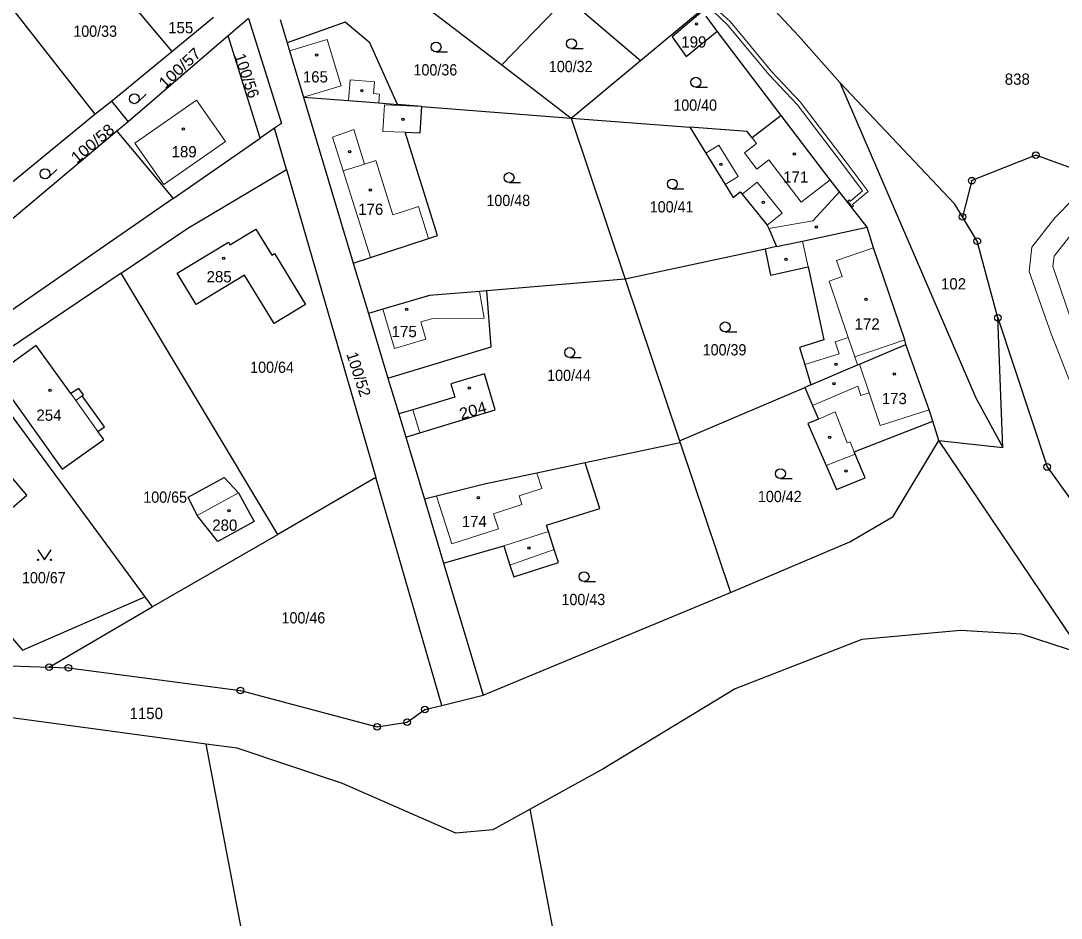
# Model space of a CAD drawing. Extents: x -758887 to -754328, y -1031688 to -1029144.
# Drawn here: x -756179.9 to -756022.6, y -1030649.6 to -1030514 of the extents above; entities that cross this region are included whole.
import ezdxf
from ezdxf.enums import TextEntityAlignment as Align

# ---------------------------------------------------------------- set-up
doc = ezdxf.new("R2010")
doc.units = 0
doc.header["$LTSCALE"] = 0.68
for name, color, linetype, lineweight in [('1', 7, 'Continuous', 25), ('13', 7, 'Continuous', 13), ('3', 7, 'Continuous', 25), ('4', 7, 'Continuous', 13), ('5', 7, 'Continuous', 25), ('8', 7, 'Continuous', 25)]:
    doc.layers.add(name, color=color, linetype=linetype, lineweight=lineweight)
doc.layers.add('2', color=7, linetype='Continuous')

msp = doc.modelspace()

# ---------------------------------------------------------------- linework, layer by layer
at = {"layer": '1'}
for p, q in [((-756145.46, -1030513.63), (-756148.51, -1030516.24)), ((-756140.69, -1030513.8), (-756139.63, -1030517.33)), ((-756074.6, -1030515.58), (-756076.28, -1030513.28)), ((-756064.96, -1030528.32), (-756074.6, -1030515.58)), ((-756148.51, -1030516.24), (-756163.67, -1030529.25)), ((-756143.72, -1030531.75), (-756148.51, -1030516.24)), ((-756096.67, -1030528.69), (-756086.2, -1030520.01)), ((-756107.17, -1030520.63), (-756096.67, -1030528.69)), ((-756166.18, -1030526.16), (-756163.67, -1030529.25)), ((-756119.28, -1030526.92), (-756122.96, -1030526.63)), ((-756189.64, -1030545.27), (-756168.68, -1030528.11)), ((-756119.28, -1030526.92), (-756096.67, -1030528.69)), ((-756096.67, -1030528.69), (-756078.73, -1030530.05)), ((-756096.67, -1030528.69), (-756088.5, -1030553.04)), ((-756165.35, -1030530.67), (-756186.8, -1030548.66)), ((-756139.7, -1030536.47), (-756126.21, -1030583.03)), ((-756065.62, -1030548.12), (-756067.38, -1030548.5)), ((-756129.64, -1030550.6), (-756127.34, -1030558.23)), ((-756088.5, -1030553.04), (-756109.44, -1030554.82)), ((-756127.34, -1030558.23), (-756124.39, -1030567.99)), ((-756031.43, -1030578.5), (-756032.2, -1030558.87)), ((-756124.39, -1030567.99), (-756122.75, -1030573.41)), ((-756060.43, -1030569), (-756061.35, -1030569.39)), ((-756122.75, -1030573.41), (-756121.7, -1030576.9)), ((-756041.1, -1030577.44), (-756042.01, -1030574.52)), ((-756121.7, -1030576.9), (-756118.86, -1030586.3)), ((-756080.19, -1030577.78), (-756094.57, -1030580.81)), ((-756080.31, -1030577.45), (-756080.19, -1030577.78)), ((-756080.19, -1030577.78), (-756072.6, -1030600.41)), ((-756041.1, -1030577.44), (-756031.43, -1030578.5)), ((-756019.33, -1030609.72), (-756041.1, -1030577.44)), ((-756126.21, -1030583.03), (-756141.03, -1030591.62)), ((-756116.24, -1030617.45), (-756126.21, -1030583.03)), ((-756115.96, -1030595.97), (-756109.97, -1030615.92)), ((-756109.97, -1030615.92), (-756072.6, -1030600.41)), ((-756175.61, -1030611.67), (-756160.01, -1030602.58)), ((-756181.34, -1030611.46), (-756175.61, -1030611.67)), ((-756085.48, -1030724.4), (-756102.87, -1030633.12))]:
    msp.add_line(p, q, dxfattribs=at)
for points in [[(-756056.08, -1030523.3), (-756062.34, -1030516.25), (-756076.02, -1030501.54), (-756085.66, -1030492.03)], [(-756158.71, -1030502.76), (-756161.82, -1030505.36), (-756165.54, -1030508.47), (-756157.04, -1030518.62), (-756150.75, -1030513.43)], [(-756181.35, -1030508.64), (-756182.88, -1030509.9), (-756168.68, -1030528.11)], [(-756122.94, -1030508.54), (-756107.17, -1030520.63), (-756097.36, -1030510.47)], [(-756096.52, -1030509.6), (-756097.36, -1030510.47), (-756086.2, -1030520.01), (-756076.96, -1030512.35)], [(-756145.46, -1030513.63), (-756140.48, -1030529.53), (-756141.51, -1030530.23)], [(-756076.82, -1030512.55), (-756081.44, -1030516.41), (-756079.31, -1030519.4), (-756074.6, -1030515.58)], [(-756122.96, -1030526.63), (-756127.12, -1030517.32), (-756130.87, -1030514.19), (-756139.63, -1030517.33)], [(-756168.68, -1030528.11), (-756166.18, -1030526.16), (-756157.04, -1030518.62)], [(-756139.63, -1030517.33), (-756139.27, -1030518.53), (-756137.17, -1030525.52)], [(-756056.08, -1030523.3), (-756035.51, -1030570.99), (-756031.43, -1030578.5)], [(-756037.52, -1030543.6), (-756038.67, -1030541.7), (-756056.08, -1030523.3)], [(-756137.17, -1030525.52), (-756130.34, -1030526.05), (-756125.75, -1030526.41), (-756122.96, -1030526.63)], [(-756137.17, -1030525.52), (-756129.64, -1030550.6), (-756127.04, -1030549.75)], [(-756127.04, -1030549.75), (-756118.26, -1030546.87), (-756116.89, -1030546.42), (-756121.79, -1030530.84), (-756119.52, -1030530.93), (-756119.28, -1030526.92)], [(-756163.67, -1030529.25), (-756165.35, -1030530.67), (-756156.85, -1030540.84), (-756143.72, -1030531.75)], [(-756064.96, -1030528.32), (-756069.33, -1030531.66), (-756070.06, -1030530.71), (-756078.73, -1030530.05)], [(-756051.93, -1030545.17), (-756056.13, -1030539.82), (-756057.53, -1030538.04), (-756064.96, -1030528.32)], [(-756164.69, -1030552.12), (-756154.61, -1030545.32), (-756139.7, -1030536.47), (-756141.51, -1030530.23), (-756143.72, -1030531.75)], [(-756078.73, -1030530.05), (-756076.32, -1030533.97), (-756073.39, -1030538.74), (-756072.19, -1030540.69), (-756071.14, -1030539.83), (-756070.84, -1030540.21), (-756067.03, -1030544.88), (-756066.82, -1030545.37), (-756065.62, -1030548.12)], [(-755993.12, -1030546.43), (-756026.43, -1030534.31), (-756036.12, -1030538.15), (-756037.52, -1030543.6)], [(-756156.85, -1030540.84), (-756201.34, -1030571.62), (-756205.5, -1030564.34), (-756186.8, -1030548.66), (-756189.64, -1030545.27)], [(-756032.2, -1030558.87), (-756035.29, -1030547.3), (-756037.52, -1030543.6)], [(-756065.62, -1030548.12), (-756061.71, -1030547.27), (-756051.93, -1030545.17)], [(-756046.07, -1030562.89), (-756046.24, -1030562.21), (-756050.96, -1030548.3), (-756051.93, -1030545.17)], [(-756067.38, -1030548.5), (-756088.5, -1030553.04), (-756080.31, -1030577.45), (-756061.35, -1030569.39)], [(-756067.38, -1030548.5), (-756066.54, -1030552.41), (-756060.87, -1030551.18), (-756058.5, -1030562.22), (-756062.18, -1030563.36), (-756061.38, -1030565.94), (-756060.43, -1030569)], [(-756109.44, -1030554.82), (-756110.54, -1030554.91), (-756118.11, -1030555.53), (-756125.13, -1030557.58), (-756127.34, -1030558.23)], [(-756124.39, -1030567.99), (-756108.76, -1030563.29), (-756109.44, -1030554.82)], [(-756032.2, -1030558.87), (-756024.73, -1030581.42), (-756011.92, -1030599.21), (-755999.82, -1030612.39), (-755958.6, -1030649.86), (-755949.37, -1030659.38), (-755935.92, -1030681.56), (-755917.44, -1030718.6), (-755911.04, -1030729.61), (-755902.43, -1030739.52), (-755891.11, -1030748.79), (-755870.11, -1030761.03), (-755851.89, -1030767.87), (-755819.52, -1030779.25), (-755801.51, -1030786.45), (-755788.77, -1030792.69), (-755778.96, -1030799.32), (-755771.14, -1030806.14), (-755760.1, -1030817.71)], [(-756060.43, -1030569), (-756053.4, -1030566.01), (-756053.09, -1030565.88), (-756046.07, -1030562.89)], [(-756042.01, -1030574.52), (-756042.55, -1030572.79), (-756046.07, -1030562.89)], [(-756186.42, -1030566.76), (-756205.1, -1030579.37), (-756179.64, -1030609.11), (-756161.14, -1030601.04)], [(-756121.7, -1030576.9), (-756119.55, -1030576.25), (-756108.15, -1030572.81), (-756109.8, -1030567.35), (-756114.88, -1030568.88), (-756114.27, -1030570.89), (-756120.6, -1030572.77), (-756122.75, -1030573.41)], [(-756061.35, -1030569.39), (-756060.19, -1030572.12), (-756059.31, -1030574.18), (-756060.9, -1030574.86)], [(-756060.9, -1030574.86), (-756058.16, -1030581.18), (-756056.55, -1030584.84), (-756052.25, -1030583.07), (-756053.73, -1030579.48)], [(-756053.73, -1030579.48), (-756053.88, -1030579.14), (-756042.01, -1030574.52)], [(-756072.6, -1030600.41), (-756054.54, -1030592.75), (-756048.02, -1030588.89), (-756041.1, -1030577.44)], [(-756094.57, -1030580.81), (-756101.86, -1030582.35), (-756109.79, -1030584.02), (-756117.02, -1030585.84), (-756118.86, -1030586.3), (-756115.96, -1030595.97)], [(-756115.96, -1030595.97), (-756106.86, -1030593.35), (-756105.93, -1030596.25), (-756105.37, -1030598.02), (-756098.61, -1030595.86), (-756099.23, -1030593.91), (-756100.1, -1030591.19), (-756100.4, -1030590.24), (-756092.37, -1030587.69), (-756094.57, -1030580.81)], [(-756019.33, -1030609.72), (-756028.62, -1030606.7), (-756037.84, -1030606.12), (-756052.73, -1030607.5), (-756071.91, -1030614.97), (-756091.74, -1030626.98), (-756102.87, -1030633.12)], [(-756175.61, -1030611.67), (-756172.69, -1030611.77), (-756146.69, -1030615.22), (-756126, -1030620.69), (-756121.46, -1030619.98), (-756118.82, -1030618.08), (-756116.24, -1030617.45), (-756109.97, -1030615.92)], [(-756151.84, -1030623.3), (-756180.88, -1030619.37), (-756192.51, -1030618.56)], [(-756169.3, -1030740.37), (-756130.93, -1030733.06), (-756151.84, -1030623.3)], [(-756102.87, -1030633.12), (-756108.54, -1030636.25), (-756114.1, -1030636.75), (-756131.26, -1030629.27), (-756147.15, -1030623.94), (-756151.84, -1030623.3)]]:
    msp.add_lwpolyline(points, dxfattribs=at)
for points in [[(-756153.38, -1030556.85), (-756156.23, -1030552.13), (-756148.5, -1030547.43), (-756148.26, -1030547.87), (-756144.33, -1030545.49), (-756141.95, -1030549.41), (-756141.53, -1030549.16), (-756136.84, -1030556.89), (-756141.57, -1030559.75), (-756146.04, -1030552.41)], [(-756164.69, -1030552.12), (-756186.42, -1030566.76), (-756161.14, -1030601.04), (-756160.01, -1030602.58), (-756141.03, -1030591.62)], [(-756173.65, -1030581.76), (-756167.34, -1030577.28), (-756168.21, -1030576.07), (-756167.24, -1030575.37), (-756170.59, -1030570.65), (-756170.42, -1030570.52), (-756171.12, -1030569.55), (-756172.34, -1030570.32), (-756177.54, -1030563.07), (-756183.82, -1030567.54)], [(-756191.97, -1030583.82), (-756185.58, -1030591.31), (-756178.98, -1030585.7), (-756185.35, -1030578.19)], [(-756146.95, -1030585.33), (-756144.58, -1030589.68), (-756150.11, -1030592.7), (-756153.2, -1030588.75), (-756154.57, -1030586), (-756149.13, -1030583.02)]]:
    msp.add_lwpolyline(points, close=True, dxfattribs=at)
at = {"layer": '13'}
for points in [[(-756076.19, -1030511.62), (-756073.05, -1030514.58), (-756066.79, -1030522.12), (-756062.53, -1030526.62), (-756055.76, -1030535.49), (-756052.62, -1030539.71), (-756054.47, -1030541.26), (-756054.63, -1030541.03), (-756054.85, -1030541.21), (-756054.2, -1030542.14), (-756054, -1030541.96), (-756054.14, -1030541.76), (-756051.8, -1030539.81), (-756055.28, -1030535.13), (-756062.07, -1030526.24), (-756066.35, -1030521.72), (-756072.61, -1030514.16), (-756076.46, -1030510.55)], [(-756017.9, -1030537.95), (-756023.58, -1030543.78), (-756027.07, -1030548.22), (-756027.45, -1030551.9), (-756024.1, -1030561.28), (-756019.87, -1030572.08)], [(-756020.82, -1030560.08), (-756023.85, -1030551.14), (-756023.69, -1030549.58), (-756020.94, -1030546.08)]]:
    msp.add_lwpolyline(points, dxfattribs=at)
at = {"layer": '3'}
for p, q in [((-756117.103, -1030518.7), (-756115.353, -1030518.7)), ((-756096.643, -1030518.2), (-756094.893, -1030518.2)), ((-756162.195, -1030526.305), (-756160.936, -1030525.089)), ((-756077.833, -1030524.03), (-756076.083, -1030524.03)), ((-756175.715, -1030537.665), (-756174.435, -1030536.472)), ((-756106.073, -1030538.44), (-756104.323, -1030538.44)), ((-756081.393, -1030539.4), (-756079.643, -1030539.4)), ((-756073.393, -1030561.01), (-756071.643, -1030561.01)), ((-756096.903, -1030564.88), (-756095.153, -1030564.88)), ((-756065.043, -1030583.18), (-756063.293, -1030583.18)), ((-756094.733, -1030598.75), (-756092.983, -1030598.75))]:
    msp.add_line(p, q, dxfattribs=at)
msp.add_lwpolyline([(-756177.3, -1030593.959), (-756176.3, -1030595.46), (-756175.3, -1030593.959)], dxfattribs=at)
for centre, radius in [((-756117.1029, -1030517.9498), 0.75), ((-756096.6429, -1030517.4498), 0.75), ((-756077.8329, -1030523.2798), 0.75), ((-756162.716, -1030525.7654), 0.75), ((-756176.2264, -1030537.1165), 0.75), ((-756106.0729, -1030537.6898), 0.75), ((-756081.3929, -1030538.6498), 0.75), ((-756073.3929, -1030560.2598), 0.75), ((-756096.9029, -1030564.1298), 0.75), ((-756065.0429, -1030582.4298), 0.75), ((-756177.3, -1030595.4595), 0.1), ((-756175.3, -1030595.4595), 0.1), ((-756094.7329, -1030597.9998), 0.75)]:
    msp.add_circle(centre, radius, dxfattribs=at)
at = {"layer": '4'}
for p, q in [((-756130.1, -1030522.92), (-756130.34, -1030526.05)), ((-756130.1, -1030522.92), (-756126.41, -1030523.2)), ((-756137.17, -1030525.52), (-756131.47, -1030523.81)), ((-756162.63, -1030532.46), (-756153.3, -1030525.96)), ((-756148.93, -1030532.24), (-756153.3, -1030525.96)), ((-756125.14, -1030530.7), (-756124.91, -1030526.69)), ((-756124.91, -1030526.69), (-756119.28, -1030526.92)), ((-756121.79, -1030530.84), (-756125.14, -1030530.7)), ((-756158.26, -1030538.74), (-756162.63, -1030532.46)), ((-756158.26, -1030538.74), (-756148.93, -1030532.24)), ((-756074.36, -1030532.76), (-756076.32, -1030533.97)), ((-756074.36, -1030532.76), (-756071.43, -1030537.53)), ((-756070.49, -1030533.93), (-756068.66, -1030532.53)), ((-756068.66, -1030532.53), (-756069.33, -1030531.66)), ((-756068.61, -1030536.39), (-756070.49, -1030533.93)), ((-756131.15, -1030536.67), (-756127.92, -1030535.65)), ((-756066.78, -1030535), (-756068.61, -1030536.39)), ((-756061.9, -1030541.38), (-756066.78, -1030535)), ((-756071.43, -1030537.53), (-756073.39, -1030538.74)), ((-756068.59, -1030538.38), (-756070.84, -1030540.21)), ((-756068.59, -1030538.38), (-756064.78, -1030543.05)), ((-756061.9, -1030541.38), (-756057.53, -1030538.04)), ((-756060.17, -1030544.2), (-756056.13, -1030539.82)), ((-756119.78, -1030542.08), (-756118.26, -1030546.87)), ((-756064.78, -1030543.05), (-756067.03, -1030544.88)), ((-756066.82, -1030545.37), (-756060.17, -1030544.2)), ((-756061.71, -1030547.27), (-756060.87, -1030551.18)), ((-756056.55, -1030550.2), (-756050.96, -1030548.3)), ((-756055.71, -1030552.66), (-756056.55, -1030550.2)), ((-756057.7, -1030553.33), (-756055.71, -1030552.66)), ((-756054.8, -1030561.85), (-756057.7, -1030553.33)), ((-756110.54, -1030554.91), (-756109.84, -1030558.95)), ((-756125.13, -1030557.58), (-756123.39, -1030563.51)), ((-756119.41, -1030559.49), (-756118.64, -1030562.12)), ((-756118.64, -1030562.12), (-756123.39, -1030563.51)), ((-756056.79, -1030562.53), (-756054.8, -1030561.85)), ((-756056.18, -1030564.32), (-756056.79, -1030562.53)), ((-756053.81, -1030564.78), (-756054.8, -1030561.85)), ((-756053.81, -1030564.78), (-756046.24, -1030562.21)), ((-756056.18, -1030564.32), (-756061.38, -1030565.94)), ((-756053.4, -1030566.01), (-756053.81, -1030564.78)), ((-756053.09, -1030565.88), (-756051.64, -1030570.21)), ((-756170.59, -1030570.65), (-756171.57, -1030571.38)), ((-756053.34, -1030569.2), (-756060.19, -1030572.12)), ((-756053.34, -1030569.2), (-756052.87, -1030570.62)), ((-756052.87, -1030570.62), (-756051.64, -1030570.21)), ((-756051.64, -1030570.21), (-756049.99, -1030575.14)), ((-756119.55, -1030576.25), (-756120.6, -1030572.77)), ((-756056.75, -1030573.08), (-756059.31, -1030574.18)), ((-756054.94, -1030577.78), (-756056.75, -1030573.08)), ((-756049.99, -1030575.14), (-756042.55, -1030572.79)), ((-756054.53, -1030577.62), (-756054.94, -1030577.78)), ((-756053.88, -1030579.14), (-756054.53, -1030577.62)), ((-756058.16, -1030581.18), (-756053.73, -1030579.48)), ((-756101.86, -1030582.35), (-756101.11, -1030584.69)), ((-756101.11, -1030584.69), (-756104.54, -1030585.79)), ((-756146.95, -1030585.33), (-756153.2, -1030588.75)), ((-756117.02, -1030585.84), (-756114.73, -1030593.02)), ((-756104.54, -1030585.79), (-756104.12, -1030587.12)), ((-756104.12, -1030587.12), (-756108.41, -1030588.49)), ((-756108.41, -1030588.49), (-756107.68, -1030590.77)), ((-756107.68, -1030590.77), (-756114.73, -1030593.02)), ((-756100.1, -1030591.19), (-756106.86, -1030593.35)), ((-756105.93, -1030596.25), (-756099.23, -1030593.91))]:
    msp.add_line(p, q, dxfattribs=at)
for points in [[(-756139.27, -1030518.53), (-756133.57, -1030516.82), (-756131.47, -1030523.81)], [(-756126.41, -1030523.2), (-756126.55, -1030525), (-756125.65, -1030525.07), (-756125.75, -1030526.41)], [(-756127.04, -1030549.75), (-756131.15, -1030536.67), (-756132.75, -1030531.59), (-756129.55, -1030530.44), (-756127.92, -1030535.65), (-756126.23, -1030535.12), (-756123.63, -1030543.29)], [(-756123.63, -1030543.29), (-756121.73, -1030542.69), (-756119.78, -1030542.08)], [(-756109.84, -1030558.95), (-756117.59, -1030558.96), (-756119.41, -1030559.49)], [(-756172.34, -1030570.32), (-756171.57, -1030571.38), (-756168.21, -1030576.07)]]:
    msp.add_lwpolyline(points, dxfattribs=at)
at = {"layer": '5'}
for centre in [(-756077.7368, -1030514.4592), (-756135.1668, -1030519.1592), (-756128.3268, -1030524.5692), (-756122.1068, -1030528.8792), (-756155.3268, -1030530.3492), (-756130.1868, -1030533.7592), (-756062.9268, -1030534.1292), (-756074.0568, -1030535.6592), (-756127.0368, -1030539.5492), (-756067.6368, -1030541.4192), (-756059.6068, -1030545.1392), (-756149.1968, -1030549.8892), (-756064.2168, -1030550.0392), (-756052.1168, -1030556.0792), (-756121.5668, -1030557.5992), (-756056.6368, -1030565.9092), (-756047.8468, -1030567.3692), (-756056.9668, -1030568.8392), (-756175.4468, -1030569.8492), (-756112.0868, -1030569.4892), (-756057.6268, -1030576.9492), (-756055.1268, -1030582.0192), (-756110.6968, -1030586.0792), (-756148.4168, -1030588.0392), (-756103.0668, -1030593.6492)]:
    msp.add_circle(centre, 0.175, dxfattribs=at)
at = {"layer": '8'}
for centre, radius in [((-756026.43, -1030534.3099), 0.5), ((-756026.43, -1030534.3099), 0.0303), ((-756036.12, -1030538.1499), 0.5), ((-756036.12, -1030538.1499), 0.0303), ((-756037.52, -1030543.5999), 0.5), ((-756037.52, -1030543.5999), 0.0303), ((-756035.29, -1030547.2999), 0.5), ((-756035.29, -1030547.2999), 0.0303), ((-756032.2, -1030558.8699), 0.5), ((-756032.2, -1030558.8699), 0.0303), ((-756024.73, -1030581.4199), 0.5), ((-756024.73, -1030581.4199), 0.0303), ((-756175.61, -1030611.6699), 0.5), ((-756172.69, -1030611.7699), 0.5), ((-756175.61, -1030611.6699), 0.0303), ((-756172.69, -1030611.7699), 0.0303), ((-756146.69, -1030615.2199), 0.5), ((-756146.69, -1030615.2199), 0.0303), ((-756118.82, -1030618.0799), 0.5), ((-756118.82, -1030618.0799), 0.0303), ((-756126, -1030620.6899), 0.5), ((-756126, -1030620.6899), 0.0303), ((-756121.46, -1030619.9799), 0.5), ((-756121.46, -1030619.9799), 0.0303)]:
    msp.add_circle(centre, radius, dxfattribs=at)

# ---------------------------------------------------------------- texts
at = {"layer": '2', "width": 0.95}
for s, p in [('100/33', (-756168.639, -1030516.41)), ('100/32', (-756096.749, -1030521.75)), ('100/36', (-756117.209, -1030522.25)), ('100/40', (-756077.939, -1030527.58)), ('100/48', (-756106.189, -1030541.99)), ('100/41', (-756081.499, -1030542.95)), ('100/39', (-756073.499, -1030564.56)), ('100/64', (-756141.899, -1030567.2)), ('100/44', (-756097.009, -1030568.43)), ('100/65', (-756158.059, -1030586.83)), ('100/42', (-756065.149, -1030586.73)), ('100/67', (-756176.399, -1030599.01)), ('100/43', (-756094.839, -1030602.3)), ('100/46', (-756137.159, -1030605.07))]:
    msp.add_text(s, height=1.7, dxfattribs=at).set_placement(p, align=Align.CENTER)
at = {"layer": '2'}
for s, p in [('155', (-756155.709, -1030515.88)), ('199', (-756078.139, -1030518.03)), ('165', (-756135.349, -1030523.31)), ('838', (-756029.239, -1030523.656)), ('189', (-756155.189, -1030534.63)), ('171', (-756062.739, -1030538.46)), ('176', (-756126.979, -1030543.32)), ('285', (-756149.899, -1030553.52)), ('102', (-756038.879, -1030554.59)), ('172', (-756051.939, -1030560.66)), ('175', (-756121.919, -1030561.8)), ('173', (-756047.839, -1030571.93)), ('254', (-756175.619, -1030574.44)), ('174', (-756111.329, -1030590.51)), ('1150', (-756160.92, -1030619.526))]:
    msp.add_text(s, height=1.7, dxfattribs=at).set_placement(p, align=Align.CENTER)
at = {"layer": '2', "width": 1.1}
for s, rotation, p in [('100/57', 43, (-756155.2732, -1030521.7514)), ('100/58', 40, (-756168.4884, -1030533.1654)), ('204', 16, (-756111.2993, -1030573.6918))]:
    msp.add_text(s, height=1.7, rotation=rotation, dxfattribs=at).set_placement(p, align=Align.CENTER)
at = {"layer": '2'}
for s, rotation, p in [('100/56', 289, (-756146.5094, -1030522.5608)), ('100/52', 288, (-756129.6105, -1030567.6773))]:
    msp.add_text(s, height=1.7, rotation=rotation, dxfattribs=at).set_placement(p, align=Align.CENTER)
msp.add_text('280', height=1.7, dxfattribs=at).set_placement((-756150.94, -1030591.07))

doc.saveas('drawing.dxf')
